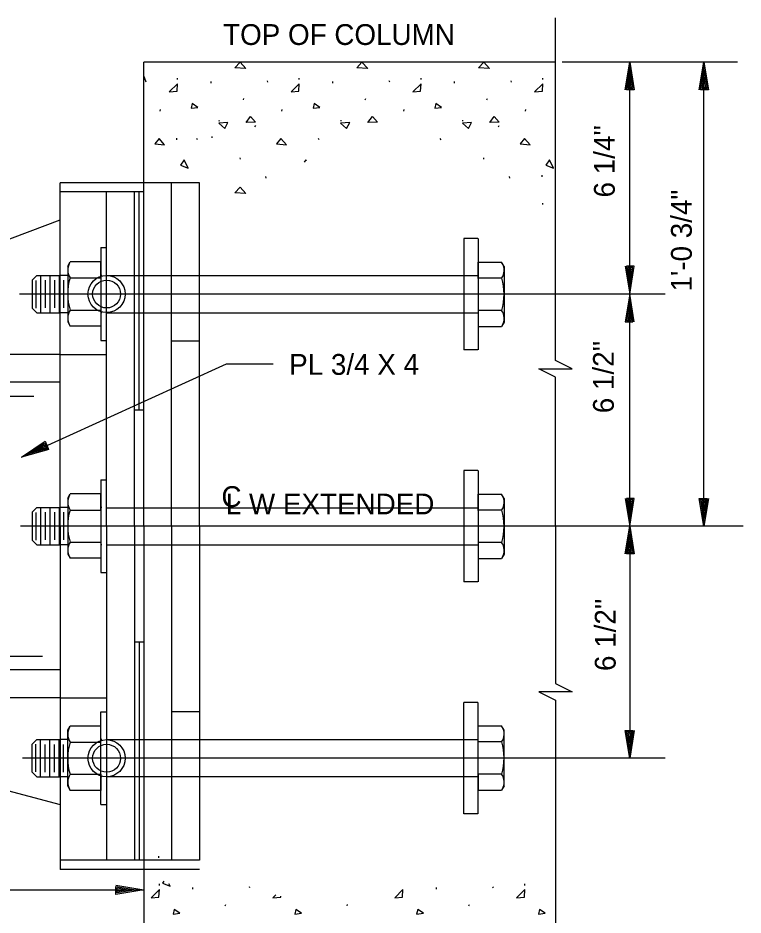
# Model space of a CAD drawing. Extents: x 0.1 to 13.5, y 0.1 to 9.5.
# Drawn here: x 4.211 to 5.839, y 1.527 to 3.54 of the extents above; entities that cross this region are included whole.
import ezdxf

# ---------------------------------------------------------------- set-up
doc = ezdxf.new("R2010")
doc.units = 0
for name, color, linetype in [('Level 10', 7, 'Continuous'), ('Level 13', 7, 'Continuous'), ('Level 2', 7, 'Continuous'), ('Level 25', 7, 'Continuous'), ('Level 3', 7, 'Continuous'), ('Level 50', 7, 'Continuous')]:
    doc.layers.add(name, color=color, linetype=linetype)

msp = doc.modelspace()

# ---------------------------------------------------------------- linework, layer by layer
at = {"layer": 'Level 10'}
for p, q in [((4.4991, 3.3963), (4.4935, 3.4103)), ((4.5694, 3.4018), (4.5694, 3.4053)), ((4.8427, 3.4018), (4.8427, 3.4053)), ((5.116, 3.4018), (5.116, 3.4053)), ((5.3894, 3.4018), (5.3894, 3.4053)), ((4.6446, 3.3937), (4.6446, 3.3974)), ((4.7724, 3.3963), (4.7714, 3.3989)), ((4.9179, 3.3937), (4.9179, 3.3974)), ((5.0457, 3.3963), (5.0447, 3.3989)), ((5.1912, 3.3937), (5.1912, 3.3974)), ((5.319, 3.3963), (5.318, 3.3989)), ((4.7172, 3.3562), (4.7185, 3.3591)), ((4.9905, 3.3562), (4.9919, 3.3591)), ((5.2638, 3.3562), (5.2652, 3.3591)), ((4.5306, 3.331), (4.5312, 3.3346)), ((4.8039, 3.331), (4.8045, 3.3346)), ((5.0772, 3.331), (5.0778, 3.3346)), ((5.3505, 3.331), (5.3511, 3.3346)), ((4.6632, 3.3082), (4.6634, 3.3109)), ((4.9365, 3.3082), (4.9367, 3.3109)), ((5.2098, 3.3082), (5.21, 3.3109)), ((4.743, 3.2957), (4.7449, 3.2988)), ((5.2896, 3.2957), (5.2915, 3.2988)), ((4.5681, 3.2667), (4.5681, 3.2705)), ((4.6142, 3.2664), (4.6125, 3.2698)), ((4.6469, 3.2712), (4.6474, 3.274)), ((4.8875, 3.2664), (4.8859, 3.2698)), ((5.1609, 3.2664), (5.1592, 3.2698)), ((4.7105, 3.2229), (4.7102, 3.2259)), ((5.2571, 3.2229), (5.2569, 3.2259)), ((4.7687, 3.1804), (4.7676, 3.1841)), ((5.3153, 3.1804), (5.3142, 3.1841)), ((5.388, 3.1834), (5.388, 3.1871)), ((5.3894, 3.1212), (5.3894, 3.1247)), ((4.5274, 1.6555), (4.5274, 1.6592)), ((4.5288, 1.5933), (4.5288, 1.5968)), ((5.3487, 1.5933), (5.3487, 1.5968)), ((4.6039, 1.5852), (4.6039, 1.589)), ((5.1506, 1.5852), (5.1506, 1.589)), ((5.2784, 1.5878), (5.2773, 1.5905)), ((4.6765, 1.5477), (4.6779, 1.5507)), ((4.9498, 1.5477), (4.9512, 1.5507)), ((5.2231, 1.5477), (5.2245, 1.5507))]:
    msp.add_line(p, q, dxfattribs=at)
for points in [[(4.6982, 3.4284), (4.7101, 3.4413), (4.7229, 3.427)], [(4.9715, 3.4284), (4.9834, 3.4413), (4.9962, 3.427)], [(5.2449, 3.4284), (5.2567, 3.4413), (5.2695, 3.427)], [(4.5685, 3.3757), (4.5694, 3.3924), (4.5509, 3.3743)], [(4.8418, 3.3757), (4.8427, 3.3924), (4.8242, 3.3743)], [(5.1151, 3.3757), (5.116, 3.3924), (5.0975, 3.3743)], [(5.3884, 3.3757), (5.3894, 3.3924), (5.3709, 3.3743)], [(4.6002, 3.3376), (4.6154, 3.3395), (4.6026, 3.3481)], [(4.8735, 3.3376), (4.8887, 3.3395), (4.8759, 3.3481)], [(5.1468, 3.3376), (5.162, 3.3395), (5.1492, 3.3481)], [(4.6622, 3.3041), (4.6755, 3.2923), (4.6827, 3.3056)], [(4.7234, 3.3056), (4.7334, 3.3189), (4.7447, 3.3061)], [(4.9355, 3.3041), (4.9489, 3.2923), (4.956, 3.3056)], [(4.9967, 3.3056), (5.0067, 3.3189), (5.018, 3.3061)], [(5.2089, 3.3041), (5.2222, 3.2923), (5.2293, 3.3056)], [(5.27, 3.3056), (5.28, 3.3189), (5.2914, 3.3061)], [(4.5405, 3.2552), (4.5282, 3.2694), (4.5182, 3.2576)], [(4.8139, 3.2552), (4.8015, 3.2694), (4.7915, 3.2576)], [(5.3605, 3.2552), (5.3481, 3.2694), (5.3382, 3.2576)], [(4.5762, 3.2096), (4.5933, 3.203), (4.5843, 3.2214)], [(4.6982, 3.1478), (4.7101, 3.1607), (4.7229, 3.1464)], [(4.5278, 1.5672), (4.5288, 1.5839), (4.5103, 1.5658)], [(5.0744, 1.5672), (5.0754, 1.5839), (5.0569, 1.5658)], [(5.3478, 1.5672), (5.3487, 1.5839), (5.3302, 1.5658)], [(4.5595, 1.5291), (4.5747, 1.531), (4.5619, 1.5396)], [(4.8328, 1.5291), (4.848, 1.531), (4.8353, 1.5396)], [(5.1061, 1.5291), (5.1213, 1.531), (5.1086, 1.5396)], [(5.3794, 1.5291), (5.3946, 1.531), (5.3819, 1.5396)]]:
    msp.add_lwpolyline(points, close=True, dxfattribs=at)
for points in [[(4.8576, 3.2214), (4.854, 3.2162)], [(4.8588, 3.2191), (4.8576, 3.2214)], [(5.4042, 3.2214), (5.3962, 3.2096)], [(5.3962, 3.2096), (5.4132, 3.203)], [(5.4132, 3.203), (5.4042, 3.2214)], [(4.5388, 1.6031), (4.5356, 1.5984)], [(4.5356, 1.5984), (4.5526, 1.5918)], [(4.5526, 1.5918), (4.5503, 1.5966)], [(4.7318, 1.5878), (4.7309, 1.59)], [(4.7903, 1.5724), (4.7836, 1.5658)], [(4.7836, 1.5658), (4.8011, 1.5672)], [(4.8011, 1.5672), (4.8013, 1.5691)]]:
    msp.add_lwpolyline(points, dxfattribs=at)
at = {"layer": 'Level 13'}
for points in [[(5.4175, 2.7343), (5.38, 2.7529), (5.455, 2.7529), (5.4175, 2.7716)], [(5.4175, 2.0467), (5.455, 2.0281), (5.3801, 2.0281), (5.4175, 2.0093)]]:
    msp.add_lwpolyline(points, dxfattribs=at)
at = {"layer": 'Level 2'}
for p, q in [((5.4175, 2.7716), (5.4175, 3.5402)), ((4.4935, 2.3997), (4.4935, 3.4413)), ((5.4175, 3.4413), (4.4935, 3.4413)), ((5.8263, 3.4413), (5.4324, 3.4413)), ((5.7509, 2.3997), (5.7509, 3.4413)), ((4.306, 2.3997), (4.306, 3.1705)), ((4.4935, 3.1705), (4.306, 3.1705)), ((4.6185, 3.1705), (4.4935, 3.1705)), ((4.556, 2.3997), (4.556, 3.1705)), ((4.6185, 2.3997), (4.6185, 3.1705)), ((4.4935, 3.1497), (4.306, 3.1497)), ((4.4102, 2.3997), (4.4102, 3.1497)), ((4.4727, 2.3997), (4.4727, 3.1497)), ((4.4831, 2.6601), (4.4831, 3.1497)), ((5.2123, 3.0455), (5.2123, 2.7955)), ((5.2435, 3.0455), (5.2123, 3.0455)), ((5.2438, 3.0455), (5.2438, 2.7955)), ((4.3972, 3.0247), (4.3972, 2.8163)), ((4.3972, 3.0247), (4.4102, 3.0247)), ((4.323, 2.9831), (4.3286, 2.9927)), ((4.323, 2.9831), (4.323, 2.8579)), ((4.3972, 2.9927), (4.3286, 2.9927)), ((4.3972, 2.9562), (4.3972, 2.9927)), ((5.2438, 2.9558), (5.2438, 2.9923)), ((5.2438, 2.9923), (5.2968, 2.9923)), ((5.3024, 2.9826), (5.2968, 2.9923)), ((5.3024, 2.9826), (5.3024, 2.8576)), ((4.254, 2.9623), (4.2435, 2.9519)), ((4.254, 2.9623), (4.306, 2.9623)), ((4.2617, 2.9623), (4.2617, 2.8787)), ((4.2826, 2.9623), (4.2826, 2.8787)), ((4.3035, 2.9623), (4.3035, 2.8787)), ((4.323, 2.9623), (4.306, 2.9623)), ((4.3998, 2.9623), (4.3972, 2.9623)), ((4.4102, 2.9619), (5.2438, 2.9619)), ((4.2435, 2.9519), (4.2435, 2.8891)), ((4.2435, 2.9519), (4.2435, 2.8891)), ((4.2518, 2.9513), (4.2518, 2.8891)), ((4.2721, 2.9518), (4.2721, 2.8895)), ((4.293, 2.9518), (4.293, 2.8895)), ((4.3139, 2.9518), (4.3139, 2.8895)), ((4.3285, 2.9567), (4.3972, 2.9567)), ((5.2969, 2.9563), (5.2438, 2.9563)), ((5.6636, 2.9205), (4.2149, 2.9205)), ((4.4102, 2.9205), (4.4102, 2.9205)), ((5.5842, 2.3997), (5.5842, 2.9205)), ((4.254, 2.8787), (4.2435, 2.8891)), ((4.3285, 2.8843), (4.3972, 2.8843)), ((5.2969, 2.8839), (5.2438, 2.8839)), ((4.254, 2.8787), (4.306, 2.8787)), ((4.323, 2.8787), (4.306, 2.8787)), ((4.3998, 2.8787), (4.3972, 2.8787)), ((4.4102, 2.8783), (5.2438, 2.8783)), ((4.323, 2.8579), (4.3286, 2.8483)), ((4.3972, 2.8483), (4.3286, 2.8483)), ((5.2438, 2.8479), (5.2968, 2.8479)), ((5.3024, 2.8576), (5.2968, 2.8479)), ((4.3972, 2.8163), (4.4102, 2.8163)), ((4.556, 2.8158), (4.6185, 2.8158)), ((4.306, 2.7851), (3.2956, 2.7851)), ((4.306, 2.7851), (4.4102, 2.7851)), ((5.2435, 2.7955), (5.2123, 2.7955)), ((4.306, 2.7226), (3.2956, 2.7226)), ((5.4175, 2.3997), (5.4175, 2.7343)), ((4.4935, 2.6601), (4.4727, 2.6601)), ((5.2123, 2.5247), (5.2123, 2.2747)), ((5.2435, 2.5247), (5.2123, 2.5247)), ((5.2438, 2.5247), (5.2438, 2.2747)), ((4.3972, 2.5038), (4.3972, 2.2955)), ((4.3972, 2.5038), (4.4102, 2.5038)), ((4.323, 2.4622), (4.3286, 2.4719)), ((4.323, 2.4622), (4.323, 2.3371)), ((4.3972, 2.4719), (4.3286, 2.4719)), ((4.3972, 2.4353), (4.3972, 2.4719)), ((5.2438, 2.4349), (5.2438, 2.4715)), ((5.2438, 2.4715), (5.2968, 2.4715)), ((5.3024, 2.4618), (5.2968, 2.4715)), ((5.3024, 2.4618), (5.3024, 2.3367)), ((4.254, 2.4415), (4.2435, 2.431)), ((4.254, 2.4415), (4.306, 2.4415)), ((4.2617, 2.4415), (4.2617, 2.3578)), ((4.2826, 2.4415), (4.2826, 2.3578)), ((4.3035, 2.4415), (4.3035, 2.3578)), ((4.323, 2.4415), (4.306, 2.4415)), ((4.3998, 2.4415), (4.3972, 2.4415)), ((4.4102, 2.4411), (5.2438, 2.4411)), ((4.2435, 2.431), (4.2435, 2.3683)), ((4.2435, 2.431), (4.2435, 2.3683)), ((4.2518, 2.4304), (4.2518, 2.3682)), ((4.2721, 2.4309), (4.2721, 2.3687)), ((4.293, 2.4309), (4.293, 2.3687)), ((4.3139, 2.4309), (4.3139, 2.3687)), ((4.3285, 2.4358), (4.3972, 2.4358)), ((5.2969, 2.4354), (5.2438, 2.4354)), ((5.8386, 2.3997), (4.2169, 2.3997)), ((4.306, 2.3997), (4.306, 1.6288)), ((4.4102, 2.3997), (4.4102, 1.6497)), ((4.4727, 2.3997), (4.4727, 1.6497)), ((4.4935, 2.3997), (4.4935, 1.312)), ((4.556, 2.3997), (4.556, 1.6497)), ((4.6185, 2.3997), (4.6185, 1.6497)), ((5.4175, 2.3997), (5.4175, 2.0467)), ((5.5842, 2.3997), (5.5842, 1.8788)), ((4.254, 2.3578), (4.2435, 2.3683)), ((4.254, 2.3578), (4.306, 2.3578)), ((4.323, 2.3578), (4.306, 2.3578)), ((4.3285, 2.3635), (4.3972, 2.3635)), ((4.3998, 2.3578), (4.3972, 2.3578)), ((4.4102, 2.3574), (5.2438, 2.3574)), ((5.2969, 2.3631), (5.2438, 2.3631)), ((4.323, 2.3371), (4.3286, 2.3274)), ((5.3024, 2.3367), (5.2968, 2.327)), ((4.3972, 2.3274), (4.3286, 2.3274)), ((5.2438, 2.327), (5.2968, 2.327)), ((4.3972, 2.2955), (4.4102, 2.2955)), ((5.2435, 2.2747), (5.2123, 2.2747)), ((4.4935, 2.1393), (4.4727, 2.1393)), ((4.4831, 2.1393), (4.4831, 1.6497)), ((4.306, 2.0768), (3.2956, 2.0768)), ((4.306, 2.0143), (3.2956, 2.0143)), ((4.306, 2.0143), (4.4102, 2.0143)), ((5.2123, 1.7538), (5.2123, 2.0038)), ((5.2435, 2.0038), (5.2123, 2.0038)), ((5.2438, 1.7538), (5.2438, 2.0038)), ((5.4175, 2.0093), (5.4175, 1.2591)), ((4.3972, 1.7747), (4.3972, 1.983)), ((4.3972, 1.983), (4.4102, 1.983)), ((4.556, 1.9836), (4.6185, 1.9836)), ((4.323, 1.9414), (4.3286, 1.9511)), ((4.323, 1.8163), (4.323, 1.9414)), ((4.3972, 1.9511), (4.3286, 1.9511)), ((5.2438, 1.9515), (5.2968, 1.9515)), ((5.3024, 1.9418), (5.2968, 1.9515)), ((5.3024, 1.8167), (5.3024, 1.9418)), ((4.254, 1.9207), (4.2435, 1.9102)), ((4.254, 1.9207), (4.306, 1.9207)), ((4.2617, 1.837), (4.2617, 1.9207)), ((4.2826, 1.837), (4.2826, 1.9207)), ((4.3035, 1.837), (4.3035, 1.9207)), ((4.323, 1.9207), (4.306, 1.9207)), ((4.3285, 1.915), (4.3972, 1.915)), ((4.3998, 1.9207), (4.3972, 1.9207)), ((4.4102, 1.9211), (5.2438, 1.9211)), ((5.2969, 1.9154), (5.2438, 1.9154)), ((4.2435, 1.8475), (4.2435, 1.9102)), ((4.2435, 1.8475), (4.2435, 1.9102)), ((4.2518, 1.8481), (4.2518, 1.9103)), ((4.2721, 1.8476), (4.2721, 1.9098)), ((4.293, 1.8476), (4.293, 1.9098)), ((4.3139, 1.8476), (4.3139, 1.9098)), ((5.6636, 1.8788), (4.2214, 1.8788)), ((4.4102, 1.8788), (4.4102, 1.8788)), ((4.254, 1.837), (4.2435, 1.8475)), ((4.254, 1.837), (4.306, 1.837)), ((4.323, 1.837), (4.306, 1.837)), ((4.3285, 1.8427), (4.3972, 1.8427)), ((4.3972, 1.8432), (4.3972, 1.8066)), ((4.3998, 1.837), (4.3972, 1.837)), ((4.4102, 1.8374), (5.2438, 1.8374)), ((5.2438, 1.8436), (5.2438, 1.807)), ((5.2969, 1.8431), (5.2438, 1.8431)), ((4.323, 1.8163), (4.3286, 1.8066)), ((5.3024, 1.8167), (5.2968, 1.807)), ((4.3972, 1.8066), (4.3286, 1.8066)), ((5.2438, 1.807), (5.2968, 1.807)), ((4.3972, 1.7747), (4.4102, 1.7747)), ((5.2435, 1.7538), (5.2123, 1.7538)), ((4.6185, 1.6497), (4.306, 1.6497)), ((4.4935, 1.6288), (4.306, 1.6288)), ((4.6185, 1.6288), (4.4935, 1.6288))]:
    msp.add_line(p, q, dxfattribs=at)
for centre, radius in [((4.4102, 2.9205), 0.0417), ((4.4102, 2.9205), 0.0312), ((4.4102, 1.8788), 0.0417), ((4.4102, 1.8788), 0.0313)]:
    msp.add_circle(centre, radius, dxfattribs=at)
for centre, radius, start, end in [((4.3543, 2.9744), 0.0314, 149.7124, 214.511), ((5.271, 2.974), 0.0314, 325.489, 30.2876), ((4.4485, 2.921), 0.1255, 163.5034, 196.9816), ((5.1769, 2.9206), 0.1255, 343.0184, 16.4966), ((4.3543, 2.8665), 0.0314, 145.489, 210.2876), ((5.271, 2.8661), 0.0314, 329.7124, 34.511), ((4.3543, 2.4536), 0.0314, 149.7124, 214.511), ((5.271, 2.4532), 0.0314, 325.489, 30.2876), ((4.4485, 2.4001), 0.1255, 163.5034, 196.9816), ((5.1769, 2.3997), 0.1255, 343.0184, 16.4966), ((4.3543, 2.3457), 0.0314, 145.489, 210.2876), ((5.271, 2.3453), 0.0314, 329.7124, 34.511), ((4.3543, 1.9328), 0.0314, 149.7124, 214.511), ((5.271, 1.9332), 0.0314, 325.489, 30.2876), ((4.4485, 1.8784), 0.1255, 163.0184, 196.4966), ((5.1769, 1.8788), 0.1255, 343.5034, 16.9816), ((4.3543, 1.8249), 0.0314, 145.489, 210.2876), ((5.271, 1.8253), 0.0314, 329.7124, 34.511)]:
    msp.add_arc(centre, radius, start, end, dxfattribs=at)
at = {"layer": 'Level 25'}
for p, q in [((3.7227, 2.8684), (4.306, 3.0872)), ((3.7227, 1.9309), (4.306, 1.7747))]:
    msp.add_line(p, q, dxfattribs=at)
at = {"layer": 'Level 3'}
for p, q in [((5.5842, 2.9205), (5.5842, 3.4413)), ((5.5842, 2.9378), (5.5842, 2.9378)), ((5.5842, 2.9205), (5.5842, 2.9205)), ((5.5842, 2.9205), (5.5842, 2.9205)), ((5.5842, 2.9032), (5.5842, 2.9032)), ((4.2196, 2.5548), (4.6794, 2.7642)), ((4.6794, 2.7642), (4.7841, 2.7642)), ((3.8011, 2.6913), (4.2471, 2.6913)), ((4.2354, 2.562), (4.2354, 2.562)), ((4.2196, 2.5548), (4.2196, 2.5548)), ((5.5842, 2.417), (5.5842, 2.417)), ((5.5842, 2.3997), (5.5842, 2.3997)), ((5.5842, 2.3997), (5.5842, 2.3997)), ((5.5842, 2.3823), (5.5842, 2.3823)), ((3.8011, 2.108), (4.2668, 2.108)), ((5.5842, 1.8962), (5.5842, 1.8962)), ((5.5842, 1.8788), (5.5842, 1.8788)), ((3.556, 1.5835), (4.4935, 1.5835))]:
    msp.add_line(p, q, dxfattribs=at)
for points in [[(5.5739, 2.9828), (5.5842, 2.9205), (5.5945, 2.9828), (5.5769, 2.9828), (5.5842, 2.9378), (5.5912, 2.9802), (5.5799, 2.9802), (5.5842, 2.9545), (5.5879, 2.9775), (5.5832, 2.9775), (5.5842, 2.9718)], [(5.5945, 2.8582), (5.5842, 2.9205), (5.5739, 2.8582), (5.5915, 2.8582), (5.5842, 2.9032), (5.5772, 2.8608), (5.5885, 2.8608), (5.5842, 2.8865), (5.5805, 2.8635), (5.5852, 2.8635), (5.5842, 2.8692)], [(4.2806, 2.5713), (4.2196, 2.5548), (4.2721, 2.5901), (4.2794, 2.574), (4.2354, 2.562), (4.271, 2.5859), (4.2757, 2.5756), (4.2506, 2.5689), (4.27, 2.5818), (4.2719, 2.5776), (4.2663, 2.5761)], [(5.5739, 2.462), (5.5842, 2.3997), (5.5945, 2.462), (5.5769, 2.462), (5.5842, 2.417), (5.5912, 2.4593), (5.5799, 2.4593), (5.5842, 2.4337), (5.5879, 2.4567), (5.5832, 2.4567), (5.5842, 2.451)], [(5.5739, 2.3373), (5.5842, 2.3997), (5.5945, 2.3373), (5.5769, 2.3373), (5.5842, 2.3823), (5.5912, 2.34), (5.5799, 2.34), (5.5842, 2.3657), (5.5879, 2.3427), (5.5832, 2.3427), (5.5842, 2.3483)], [(5.5945, 1.9412), (5.5842, 1.8788), (5.5739, 1.9412), (5.5915, 1.9412), (5.5842, 1.8962), (5.5772, 1.9385), (5.5885, 1.9385), (5.5842, 1.9128), (5.5805, 1.9358), (5.5852, 1.9358), (5.5842, 1.9302)]]:
    msp.add_lwpolyline(points, dxfattribs=at)
at = {"layer": 'Level 50'}
for p, q in [((5.5842, 3.4413), (5.5842, 3.4413)), ((5.5842, 3.424), (5.5842, 3.424)), ((5.7509, 3.4413), (5.7509, 3.4413)), ((5.7509, 3.424), (5.7509, 3.424)), ((5.7509, 2.417), (5.7509, 2.417)), ((5.7509, 2.3997), (5.7509, 2.3997)), ((4.4762, 1.5835), (4.4762, 1.5835)), ((4.4935, 1.5835), (4.4935, 1.5835))]:
    msp.add_line(p, q, dxfattribs=at)
for points in [[(5.5739, 3.379), (5.5842, 3.4413), (5.5945, 3.379), (5.5769, 3.379), (5.5842, 3.424), (5.5912, 3.3817), (5.5799, 3.3817), (5.5842, 3.4073), (5.5879, 3.3843), (5.5832, 3.3843), (5.5842, 3.39)], [(5.7405, 3.379), (5.7509, 3.4413), (5.7612, 3.379), (5.7435, 3.379), (5.7509, 3.424), (5.7579, 3.3817), (5.7465, 3.3817), (5.7509, 3.4073), (5.7545, 3.3843), (5.7499, 3.3843), (5.7509, 3.39)], [(5.7612, 2.462), (5.7509, 2.3997), (5.7405, 2.462), (5.7582, 2.462), (5.7509, 2.417), (5.7439, 2.4593), (5.7552, 2.4593), (5.7509, 2.4337), (5.7472, 2.4567), (5.7519, 2.4567), (5.7509, 2.451)], [(4.4312, 1.5939), (4.4935, 1.5835), (4.4312, 1.5732), (4.4312, 1.5909), (4.4762, 1.5835), (4.4339, 1.5765), (4.4339, 1.5879), (4.4595, 1.5835), (4.4365, 1.5799), (4.4365, 1.5845), (4.4422, 1.5835)]]:
    msp.add_lwpolyline(points, dxfattribs=at)

# ---------------------------------------------------------------- texts
at = {"layer": 'Level 3'}
for s, height, p in [('TOP OF COLUMN', 0.046667, (4.6718, 3.4796)), ('PL 3/4 X 4', 0.04667, (4.82, 2.7393)), ('C', 0.0467, (4.668, 2.4426)), ('L W EXTENDED', 0.046667, (4.6777, 2.4261))]:
    msp.add_text(s, height=height, dxfattribs=at).set_placement(p)
for s, p in [("6 1/4''", (5.5507, 3.1373)), ('1\'-0 3/4"', (5.7236, 2.9263)), ("6 1/2''", (5.5486, 2.6531)), ("6 1/2''", (5.5527, 2.0745))]:
    msp.add_text(s, height=0.04667, rotation=90, dxfattribs=at).set_placement(p)

doc.saveas('drawing.dxf')
